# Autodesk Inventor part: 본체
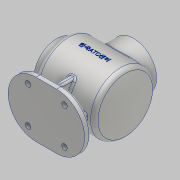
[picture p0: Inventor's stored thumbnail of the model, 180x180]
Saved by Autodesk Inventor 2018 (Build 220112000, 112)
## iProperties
Created: 2023-01
Part Number: 본체
Material: 알루미늄 6061
Document SubType Name: Modeling
Designer: home
Density: 2.7 g/cm^3
Appearance: 알루미늄 - 평지
Mass: 1034.39 g
Surface Area: 1157.53 cm^2
Volume: 383.109 cm^3
Author: home
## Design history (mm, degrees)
sketch "스케치1"
  geometry: L1 (51, -50)-(-48.087, -50); L2 (63, 0)-(63, -38); L3 (63, -38)-(51, -38); L4 (51, -38)-(51, -50); L5 (63, -27)-(46, -27); L6 (46, -27)-(46, -45); L7 (46, -45)-(-44.83, -45); L8 (63, 0)-(-59, 0); L9 (0, -78.298)-(0, 115.666) reference; A1 r 120 centre (61, 0) between (-59, 0) and (-48.087, -50); A2 r 115 centre (61, 0) between (-54, 0) and (-44.83, -45)
  constraints: 16 end point, 4 horizontal, 4 point on circle, 3 perpendicular, 2 centre point, 2 point on line, 1 parallel
  dimensions: "d8" = 122 distance from line of L8.end L2; "d9" = 100 diameter of L1 L8; "d10" = 76 diameter of L3 L8; "d11" = 5 radial gap between concentric circles of A1 A2; "d12" = 90 diameter of L7 L8; "d13" = 54 diameter of L5 L8; "d17" = 2 distance from line of A1.centre L2; "d18" = 12 distance between parallel lines of L4 L2; "d19" = 17 distance between parallel lines of L6 L2; "d20" = 120 radius of A1; "d51" = 59 distance from line of L8.end L9; "d52" = 153.66597 distance from line of L9.end L3
revolve "회전1" sketch "스케치1" stored, may be unused: angle "d21" = 90 deg
node "작업 평면1"
sketch "스케치2"
  geometry: L1 (63, 38)-(63, -38) reference; L2 (17, -46)-(-17, -46); L3 (17, 46)-(-17, 46); A1 r 46 centre (-17, 0) between (-17, 46) and (-17, -46); A2 r 46 centre (17, 0) between (17, -46) and (17, 46); 2 further points
  constraints: 4 end point, 4 point on circle, 4 tangent, 2 centre point, 2 horizontal, 1 horizontal alignment, 1 midpoint
  dimensions: "d26" = 46 radius of A2; "d27" = 8 distance from line of L1.start L3; "d28" = 80 distance from line of L3.end L1
extrude "돌출1" join sketch "스케치2" distance "d29" = 10; taper "d30" = 0 deg
sketch "스케치4"
  geometry: L1 (-17, 46)-(17, 46) reference; L2 (17, -46)-(-17, -46) reference; A1 r 46 centre (17, 0) between (17, -46) and (17, 46) reference; A2 r 46 centre (-17, 0) between (-17, 46) and (-17, -46) reference; 5 further points
  constraints: 2 horizontal alignment, 2 vertical alignment
  dimensions: "d35" = 60 distance of point (-30, -30) point (30, -30); "d36" = 30 horizontal distance of point (0, 0) point (30, -30); "d37" = 60 distance of point (30, 30) point (30, -30); "d38" = 30 horizontal distance of point (0, 0) point (30, 30)
hole "구멍1" sketch "스케치4" at (30, -30), (-30, -30), (30, 30), (-30, 30) diameter "d39" = 9; stored, may be unused: countersink angle "d43" = 90 deg, drill point angle "d45" = 118 deg; dims "d40" = 6, "d41" = 4, "d42" = 2, "d44" = 8
sketch "스케치5"
  geometry: L1 (5, -35)-(-5, -35); L2 (-5, -35)-(-5, 35); L3 (-5, 35)-(5, 35); L4 (5, 35)-(5, -35); A1 r 46 centre (17, 0) between (17, -46) and (17, 46) reference; A2 r 46 centre (-17, 0) between (-17, 46) and (-17, -46) reference; 2 further points
  constraints: 8 end point, 2 parallel, 1 horizontal, 1 horizontal alignment, 1 midpoint, 1 perpendicular
  dimensions: "d46" = 10 distance of L2.end L3.end; "d47" = 70 distance of L1.end L2.end; "d114" = 12 distance from line of A1.end L4
extrude "돌출3" join sketch "스케치5" stored distance "d54" = 10; taper "d55" = 0 deg
sketch "스케치6"
  geometry: L1 (-51, -50)-(48.087, -50) reference; L2 (-17, -70)-(17, -70) reference; L3 (-17, -80)-(-17, -80) reference; L4 (-17, -80)-(-17, -70) reference; L5 (-17, -70)-(-17, -70) reference; L6 (-17, -80)-(-17, -70) reference; L7 (-34.5, -70)-(-25.5, -70) reference; L8 (-17, -70)-(-63, -70) reference; L9 (-34.641, -50)-(-40, -70); 1 further point
  constraints: 2 end point, 1 midpoint, 1 point on line
  dimensions: "d56" = 105 deg angle of L8 L9; "d57" = 23 distance of L8.end L9.end
feature "리브1" sketch "스케치6" dims "d58" = 1, "d59" = 10, "d60" = 0, "d61" = 0, "d62" = 1, "d63" = 1
node "작업 평면2"
sketch "스케치8"
  geometry: C1 r 38 at (0, 0); 1 further point
  constraints: 1 centre point, 1 coincident
  dimensions: "d65" = 76 diameter of C1
extrude "돌출4" join sketch "스케치8" stored distance "d66" = 10; taper "d67" = 0 deg
hole "구멍2" diameter "d70" = 54; stored, may be unused: countersink angle "d74" = 90 deg, drill point angle "d76" = 118 deg; dims "d68" = 10, "d69" = 10, "d71" = 6, "d72" = 4, "d73" = 2, "d75" = 8
sketch "스케치9"
  geometry: 5 further points
  constraints: 5 other
  dimensions: "d80" = 360 deg dimension on point (0, 0) point (0, -32.5) (derived); "d115" = 32.5 distance of point (32.5, 0) point (0, 0)
hole "구멍3" sketch "스케치9" at (0, -32.5), (32.5, 0), (0, 32.5), (-32.5, 0) diameter "d82" = 3.242; stored, may be unused: countersink angle "d86" = 90 deg, drill point angle "d88" = 118 deg; dims "d83" = 8, "d84" = 4, "d85" = 2, "d87" = 10
sketch "스케치10"
  geometry: 5 further points
  constraints: 5 other
  dimensions: "d92" = 360 deg dimension on point (0, 0) point (0, 32.5) (derived); "d116" = 32.5 distance of point (32.5, 0) point (0, 0)
hole "구멍4" sketch "스케치10" at (0, 32.5), (-32.5, 0), (0, -32.5), (32.5, 0) diameter "d94" = 3.242; stored, may be unused: countersink angle "d98" = 90 deg, drill point angle "d100" = 118 deg; dims "d95" = 8, "d96" = 4, "d97" = 2, "d99" = 10
fillet "모깎기1" dims "d101" = 3
fillet "모깎기2" dims "d102" = 3
fillet "모깎기3" dims "d103" = 8
fillet "모깎기4" dims "d104" = 3
fillet "모깎기5" dims "d105" = 8
chamfer "모따기1" distance "d106" = 1; stored, may be unused: second distance "d107" = 2, angle "d108" = 45 deg
fillet "모깎기6" dims "d109" = 3
node "작업 평면3"
sketch "스케치11"
  geometry: L1 (-61.544, -38)-(-61.544, 38) reference; L2 (18.456, -80)-(-15.544, -80) reference; 2 further points
  constraints: 1 other
  dimensions: "d110" = 63 distance from line of point (1.456, 0) L1; "d111" = 80 distance from line of point (1.456, 0) L2
feature "엠보싱1" sketch "스케치11" dims "d26" = 46, "d112" = 0.5, "d113" = 0
node "솔리드1"
mirror "미러1"
node "투영된 루프1"
node "투영된 루프2"
other parameters: "d3" = 122, "d23" = 92, "d24" = 92, "d64" = -144
